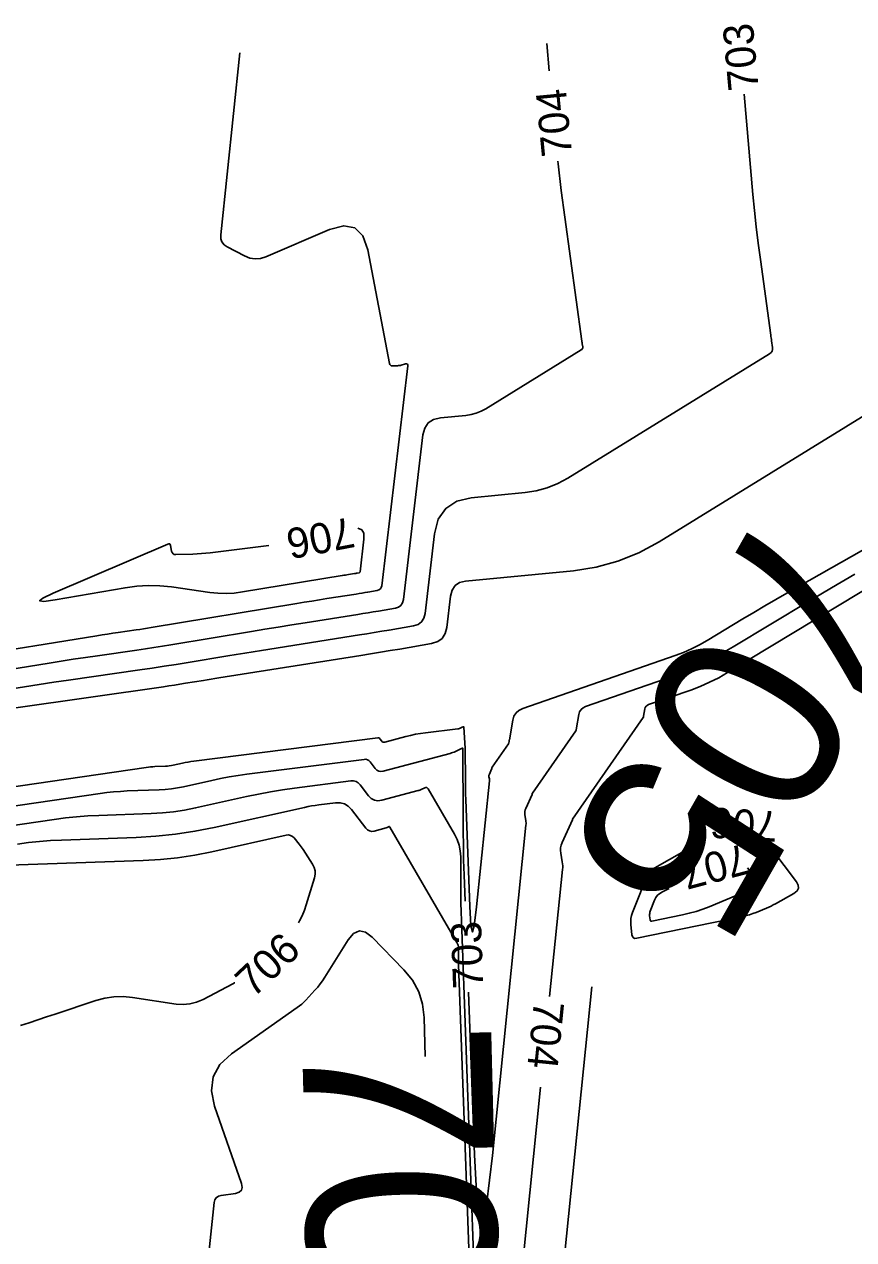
# Model space of a CAD drawing. Extents: x -468541894 to 3393103, y -306086142 to 1227927.
# Drawn here: x 1843132.3 to 1843241.8, y 539573.5 to 539733.9 of the extents above; entities that cross this region are included whole.
import ezdxf

# ---------------------------------------------------------------- set-up
doc = ezdxf.new("R2010")
doc.units = 0
doc.layers.add('DT_X_Contour_Minor', color=7, linetype='Continuous')
doc.layers.add('Level 19', color=7, linetype='Continuous')

msp = doc.modelspace()

# ---------------------------------------------------------------- linework, layer by layer
at = {"layer": 'DT_X_Contour_Minor'}
for points in [[(1843106.87, 539647.58), (1843141.86, 539653.23), (1843142.57, 539653.34), (1843143.28, 539653.45), (1843144, 539653.56), (1843144.71, 539653.66), (1843147.05, 539654), (1843147.55, 539654.07), (1843148.05, 539654.15), (1843148.55, 539654.23), (1843149.05, 539654.31), (1843168.27, 539657.48), (1843169.26, 539657.64), (1843170.25, 539657.8), (1843171.25, 539657.96), (1843172.24, 539658.12), (1843176.12, 539658.73), (1843176.5, 539658.79), (1843176.88, 539658.86), (1843177.26, 539658.92), (1843177.64, 539658.99), (1843178.88, 539659.2), (1843179.12, 539659.27), (1843179.3, 539659.4), (1843179.42, 539659.59), (1843179.48, 539659.83), (1843182.92, 539688.84), (1843182.92, 539688.99), (1843182.87, 539689.08), (1843182.77, 539689.12), (1843182.62, 539689.1), (1843182.06, 539688.93), (1843181.94, 539688.9), (1843181.81, 539688.88), (1843181.69, 539688.87), (1843181.57, 539688.86), (1843180.87, 539688.84), (1843180.73, 539688.85), (1843180.63, 539688.91), (1843180.56, 539689), (1843180.51, 539689.13), (1843177.64, 539704.13), (1843177, 539705.98), (1843175.94, 539707.05), (1843174.47, 539707.33), (1843172.57, 539706.82), (1843164.2, 539703.24), (1843163.48, 539703.02), (1843162.77, 539702.96), (1843162.06, 539703.07), (1843161.37, 539703.35), (1843159.1, 539704.53), (1843158.68, 539704.82), (1843158.39, 539705.19), (1843158.25, 539705.62), (1843158.24, 539706.13), (1843160.77, 539730.14)], [(1843201.58, 539727.77), (1843201.26, 539731.4)], [(1843130.38, 539646.19), (1843132.32, 539646.49), (1843134.26, 539646.79), (1843136.19, 539647.08), (1843138.13, 539647.37), (1843147.56, 539648.73), (1843149.16, 539648.96), (1843150.76, 539649.2), (1843152.36, 539649.45), (1843153.95, 539649.71), (1843159.16, 539650.57), (1843160.28, 539650.76), (1843161.4, 539650.94), (1843162.51, 539651.12), (1843163.63, 539651.29), (1843176.53, 539653.33), (1843177.52, 539653.49), (1843178.5, 539653.65), (1843179.48, 539653.81), (1843180.46, 539653.98), (1843183.67, 539654.53), (1843184.28, 539654.72), (1843184.74, 539655.06), (1843185.05, 539655.53), (1843185.21, 539656.15), (1843186.46, 539666.67), (1843186.95, 539668.59), (1843187.93, 539670.03), (1843189.38, 539670.97), (1843191.31, 539671.43), (1843198.4, 539672.12), (1843199.89, 539672.35), (1843201.33, 539672.74), (1843202.71, 539673.3), (1843204.04, 539674.02), (1843230.68, 539690.43), (1843230.88, 539690.59), (1843231.01, 539690.78), (1843231.07, 539691), (1843231.07, 539691.26), (1843230.95, 539692.14), (1843230.92, 539692.33), (1843230.9, 539692.52), (1843230.87, 539692.71), (1843230.84, 539692.9), (1843229.47, 539702.89), (1843229.19, 539705.03), (1843228.93, 539707.17), (1843228.7, 539709.32), (1843228.49, 539711.47), (1843227.31, 539724.7)], [(1843113.71, 539646.09), (1843135.58, 539649.62), (1843137.18, 539649.87), (1843138.77, 539650.12), (1843140.36, 539650.36), (1843141.96, 539650.59), (1843147.17, 539651.34), (1843148.29, 539651.51), (1843149.4, 539651.68), (1843150.52, 539651.85), (1843151.63, 539652.03), (1843162.27, 539653.79), (1843164.05, 539654.08), (1843165.83, 539654.37), (1843167.6, 539654.65), (1843169.38, 539654.94), (1843176.33, 539656.03), (1843177.01, 539656.14), (1843177.69, 539656.25), (1843178.37, 539656.37), (1843179.05, 539656.48), (1843181.28, 539656.87), (1843181.7, 539657), (1843182.02, 539657.23), (1843182.24, 539657.56), (1843182.35, 539657.99), (1843184.92, 539679.72), (1843185.16, 539680.62), (1843185.62, 539681.3), (1843186.3, 539681.75), (1843187.22, 539681.96), (1843190.57, 539682.29), (1843191.27, 539682.4), (1843191.95, 539682.59), (1843192.61, 539682.85), (1843193.23, 539683.19), (1843205.83, 539690.95), (1843205.92, 539691.02), (1843205.98, 539691.11), (1843206.01, 539691.22), (1843206.01, 539691.34), (1843205.95, 539691.76), (1843205.94, 539691.85), (1843205.93, 539691.93), (1843205.92, 539692.02), (1843205.9, 539692.11), (1843203.65, 539708.46), (1843203.19, 539711.97), (1843202.77, 539715.48), (1843202.73, 539715.83)], [(1843131.19, 539643.7), (1843150.66, 539646.5), (1843151.39, 539646.6), (1843152.12, 539646.71), (1843152.84, 539646.83), (1843153.57, 539646.95), (1843155.95, 539647.34), (1843156.46, 539647.42), (1843156.97, 539647.51), (1843157.47, 539647.59), (1843157.98, 539647.67), (1843176.74, 539650.63), (1843178.02, 539650.83), (1843179.31, 539651.04), (1843180.59, 539651.26), (1843181.88, 539651.47), (1843186.07, 539652.2), (1843186.87, 539652.45), (1843187.47, 539652.88), (1843187.87, 539653.51), (1843188.08, 539654.32), (1843188.57, 539658.46), (1843188.77, 539659.25), (1843189.17, 539659.84), (1843189.77, 539660.23), (1843190.56, 539660.42), (1843204.78, 539661.81), (1843207.78, 539662.27), (1843210.66, 539663.06), (1843213.43, 539664.17), (1843216.09, 539665.61), (1843255.53, 539689.92)], [(1843271.99, 539680.96), (1843232.97, 539658.85), (1843231.51, 539658.01), (1843230.05, 539657.17), (1843228.6, 539656.31), (1843227.16, 539655.45), (1843222.46, 539652.61), (1843221.44, 539652.03), (1843220.39, 539651.5), (1843219.32, 539651.03), (1843218.22, 539650.62), (1843198.09, 539643.61), (1843197.59, 539643.37), (1843197.21, 539643.04), (1843196.94, 539642.6), (1843196.78, 539642.08), (1843196.33, 539639.5), (1843196.32, 539639.44), (1843196.32, 539639.38), (1843196.31, 539639.33), (1843196.3, 539639.27), (1843196.26, 539639.08), (1843196.25, 539639.05), (1843196.24, 539639.01), (1843196.22, 539638.97), (1843196.2, 539638.94), (1843194.06, 539635.86), (1843194.04, 539635.84), (1843194.03, 539635.81), (1843194.03, 539635.79), (1843194.02, 539635.77), (1843194.01, 539635.68), (1843194.01, 539635.67), (1843194.01, 539635.65), (1843194, 539635.63), (1843193.99, 539635.62), (1843193.69, 539634.94), (1843193.66, 539634.86), (1843193.64, 539634.78), (1843193.64, 539634.7), (1843193.64, 539634.61), (1843193.69, 539634.34), (1843193.7, 539634.28), (1843193.7, 539634.22), (1843193.7, 539634.16), (1843193.7, 539634.1), (1843192.01, 539617.45), (1843191.7, 539614.96), (1843191.45, 539614.13), (1843191.24, 539614.97), (1843191.1, 539617.48), (1843190.58, 539631.6), (1843190.56, 539632.33), (1843190.54, 539633.06), (1843190.53, 539633.79), (1843190.53, 539634.52), (1843190.52, 539637.89), (1843190.52, 539637.91), (1843190.52, 539637.93), (1843190.52, 539637.95), (1843190.51, 539637.97), (1843190.51, 539638.03), (1843190.51, 539638.05), (1843190.51, 539638.06), (1843190.51, 539638.07), (1843190.51, 539638.09), (1843190.51, 539638.26), (1843190.5, 539638.3), (1843190.5, 539638.34), (1843190.5, 539638.37), (1843190.5, 539638.41), (1843190.32, 539641.17), (1843190.32, 539641.2), (1843190.3, 539641.22), (1843190.28, 539641.23), (1843190.24, 539641.22), (1843190.11, 539641.16), (1843190.08, 539641.15), (1843190.06, 539641.14), (1843190.03, 539641.13), (1843190, 539641.12), (1843189.76, 539641), (1843189.7, 539640.98), (1843189.65, 539640.96), (1843189.59, 539640.94), (1843189.53, 539640.93), (1843185.28, 539640.43), (1843184.62, 539640.34), (1843183.96, 539640.22), (1843183.3, 539640.08), (1843182.65, 539639.92), (1843179.88, 539639.18), (1843179.76, 539639.16), (1843179.66, 539639.18), (1843179.56, 539639.23), (1843179.48, 539639.32), (1843179.23, 539639.64)], [(1843136.37, 539657.96), (1843145.6, 539659.56), (1843147.14, 539659.77), (1843148.67, 539659.85), (1843150.21, 539659.81), (1843151.75, 539659.66), (1843156.78, 539658.95), (1843157.86, 539658.84), (1843158.94, 539658.81), (1843160.01, 539658.86), (1843161.09, 539659), (1843174.27, 539661.17), (1843174.48, 539661.21), (1843174.68, 539661.24), (1843174.89, 539661.27), (1843175.1, 539661.31), (1843175.91, 539661.44), (1843175.99, 539661.45), (1843176.07, 539661.46), (1843176.15, 539661.47), (1843176.23, 539661.49), (1843176.49, 539661.53), (1843176.54, 539661.55), (1843176.58, 539661.58), (1843176.6, 539661.61), (1843176.62, 539661.66), (1843177.13, 539665.97), (1843177.11, 539666.74), (1843176.84, 539667.22), (1843176.33, 539667.41), (1843176.32, 539667.41)], [(1843164.56, 539665.15), (1843156.85, 539664.17), (1843156.27, 539664.11), (1843155.7, 539664.06), (1843155.12, 539664.02), (1843154.54, 539664), (1843152.3, 539663.94), (1843152.09, 539663.96), (1843151.93, 539664.05), (1843151.82, 539664.19), (1843151.75, 539664.39), (1843151.61, 539665.13), (1843151.56, 539665.27), (1843151.49, 539665.34), (1843151.38, 539665.36), (1843151.25, 539665.33), (1843136.1, 539658.85), (1843134.73, 539658.2), (1843134.32, 539657.84), (1843134.87, 539657.75), (1843136.37, 539657.96)], [(1843251.19, 539664.09), (1843225.15, 539648.36), (1843223.97, 539647.69), (1843222.77, 539647.08), (1843221.53, 539646.54), (1843220.27, 539646.06), (1843214.7, 539644.13), (1843214.52, 539644.04), (1843214.38, 539643.92), (1843214.28, 539643.76), (1843214.22, 539643.57), (1843214.06, 539642.63), (1843214.06, 539642.61), (1843214.05, 539642.59), (1843214.05, 539642.57), (1843214.05, 539642.55), (1843214.04, 539642.48), (1843214.03, 539642.47), (1843214.03, 539642.45), (1843214.02, 539642.44), (1843214.01, 539642.43), (1843204.68, 539629.04), (1843204.68, 539629.03), (1843204.67, 539629.02), (1843204.67, 539629.01), (1843204.67, 539628.99), (1843204.66, 539628.95), (1843204.66, 539628.95), (1843204.66, 539628.94), (1843204.66, 539628.93), (1843204.66, 539628.92)], [(1843241.92, 539661.37), (1843238.86, 539659.56), (1843235.82, 539657.74), (1843225.89, 539651.74), (1843223.74, 539650.52), (1843221.53, 539649.41), (1843219.26, 539648.42), (1843216.94, 539647.54), (1843206.39, 539643.87), (1843206.06, 539643.71), (1843205.8, 539643.48), (1843205.61, 539643.18), (1843205.5, 539642.82), (1843205.2, 539641.06), (1843205.19, 539641.03), (1843205.18, 539640.99), (1843205.18, 539640.95), (1843205.17, 539640.91), (1843205.15, 539640.78), (1843205.14, 539640.76), (1843205.13, 539640.73), (1843205.12, 539640.71), (1843205.11, 539640.68), (1843199.37, 539632.45), (1843199.36, 539632.43), (1843199.35, 539632.41), (1843199.35, 539632.4), (1843199.34, 539632.38), (1843199.34, 539632.32), (1843199.34, 539632.31), (1843199.33, 539632.29), (1843199.33, 539632.28), (1843199.33, 539632.27), (1843198.49, 539630.43), (1843198.41, 539630.23), (1843198.37, 539630.02), (1843198.36, 539629.8), (1843198.38, 539629.58), (1843198.5, 539628.86), (1843198.52, 539628.71), (1843198.53, 539628.55), (1843198.53, 539628.39), (1843198.52, 539628.24), (1843194.11, 539584.64), (1843193.3, 539578.12), (1843192.63, 539575.96), (1843192.1, 539578.16), (1843191.71, 539584.72), (1843190.93, 539606.2)], [(1843179.23, 539639.64), (1843179.17, 539639.7), (1843179.11, 539639.74), (1843179.03, 539639.76), (1843178.95, 539639.76), (1843154.67, 539636.67), (1843154.29, 539636.61), (1843153.92, 539636.55), (1843153.55, 539636.48), (1843153.18, 539636.4), (1843151.97, 539636.14), (1843151.71, 539636.08), (1843151.44, 539636.04), (1843151.18, 539636.02), (1843150.92, 539636), (1843149.55, 539635.95), (1843149.26, 539635.94), (1843148.97, 539635.92), (1843148.68, 539635.89), (1843148.39, 539635.85), (1843123.31, 539632.18)], [(1843190.49, 539618.2), (1843190.37, 539621.69), (1843190.3, 539623.6), (1843190.26, 539625.51), (1843190.23, 539627.42), (1843190.22, 539629.34), (1843190.19, 539638.26), (1843190.19, 539638.26), (1843190.19, 539638.26), (1843190.19, 539638.26), (1843190.19, 539638.26), (1843190.19, 539638.26), (1843190.19, 539638.27), (1843190.19, 539638.27), (1843190.19, 539638.27), (1843190.19, 539638.27), (1843190.19, 539638.27), (1843190.19, 539638.28), (1843190.19, 539638.28), (1843190.19, 539638.28), (1843190.19, 539638.28), (1843190.18, 539638.37), (1843190.18, 539638.39), (1843190.17, 539638.4), (1843190.16, 539638.4), (1843190.15, 539638.39), (1843190.07, 539638.36), (1843190.05, 539638.35), (1843190.04, 539638.35), (1843190.02, 539638.34), (1843190.01, 539638.33), (1843189.21, 539637.96), (1843189.04, 539637.88), (1843188.86, 539637.82), (1843188.69, 539637.76), (1843188.51, 539637.7), (1843179.68, 539635.34), (1843179.37, 539635.3), (1843179.09, 539635.35), (1843178.83, 539635.48), (1843178.61, 539635.71), (1843177.94, 539636.59), (1843177.78, 539636.76), (1843177.61, 539636.86), (1843177.4, 539636.92), (1843177.18, 539636.91), (1843161.68, 539634.94), (1843160.52, 539634.77), (1843159.36, 539634.59), (1843158.21, 539634.37), (1843157.06, 539634.13), (1843153.33, 539633.3), (1843152.52, 539633.14), (1843151.72, 539633.02), (1843150.9, 539632.93), (1843150.09, 539632.89), (1843145.88, 539632.74), (1843144.98, 539632.69), (1843144.08, 539632.62), (1843143.19, 539632.53), (1843142.3, 539632.41), (1843125.38, 539629.94)], [(1843192.32, 539551.95), (1843190.01, 539615.66), (1843189.97, 539616.81), (1843189.94, 539617.96), (1843189.93, 539619.11), (1843189.92, 539620.27), (1843189.91, 539624.03), (1843189.85, 539624.83), (1843189.7, 539625.59), (1843189.45, 539626.33), (1843189.09, 539627.04), (1843185.61, 539633.02), (1843185.53, 539633.13), (1843185.42, 539633.19), (1843185.3, 539633.2), (1843185.17, 539633.16), (1843184.7, 539632.94), (1843184.6, 539632.9), (1843184.5, 539632.86), (1843184.4, 539632.82), (1843184.29, 539632.79), (1843179.49, 539631.51), (1843178.98, 539631.44), (1843178.52, 539631.51), (1843178.11, 539631.73), (1843177.74, 539632.1), (1843176.65, 539633.55), (1843176.39, 539633.81), (1843176.1, 539633.98), (1843175.77, 539634.07), (1843175.41, 539634.06), (1843167.97, 539633.12), (1843166.38, 539632.89), (1843164.8, 539632.64), (1843163.22, 539632.34), (1843161.65, 539632.01), (1843154.9, 539630.51), (1843153.45, 539630.22), (1843151.99, 539630), (1843150.52, 539629.85), (1843149.04, 539629.76), (1843142.15, 539629.52), (1843140.67, 539629.45), (1843139.2, 539629.33), (1843137.73, 539629.18), (1843136.26, 539628.99), (1843127.45, 539627.7)], [(1843192.93, 539519.19), (1843189.64, 539609.82), (1843189.63, 539610.11), (1843189.63, 539610.41), (1843189.62, 539610.71), (1843189.62, 539611.01), (1843189.62, 539611.98), (1843189.6, 539612.18), (1843189.56, 539612.38), (1843189.5, 539612.57), (1843189.41, 539612.76), (1843180.56, 539627.96), (1843180.53, 539628.01), (1843180.49, 539628.03), (1843180.44, 539628.03), (1843180.39, 539628.02), (1843180.21, 539627.93), (1843180.18, 539627.92), (1843180.14, 539627.9), (1843180.1, 539627.89), (1843180.06, 539627.87), (1843178.48, 539627.45), (1843178.16, 539627.41), (1843177.87, 539627.46), (1843177.61, 539627.6), (1843177.38, 539627.83), (1843175.51, 539630.3), (1843175.07, 539630.75), (1843174.58, 539631.05), (1843174.01, 539631.19), (1843173.39, 539631.18), (1843171.17, 539630.9), (1843170.7, 539630.83), (1843170.22, 539630.76), (1843169.75, 539630.67), (1843169.28, 539630.57), (1843157.38, 539627.92), (1843154.83, 539627.42), (1843152.25, 539627.03), (1843149.67, 539626.76), (1843147.06, 539626.6), (1843137.21, 539626.26), (1843135.76, 539626.19), (1843134.31, 539626.07), (1843132.86, 539625.92), (1843131.41, 539625.73)], [(1843204.66, 539628.92), (1843203.29, 539625.93), (1843203.17, 539625.59), (1843203.1, 539625.25), (1843203.08, 539624.9), (1843203.11, 539624.55), (1843203.31, 539623.38), (1843203.35, 539623.13), (1843203.37, 539622.88), (1843203.37, 539622.63), (1843203.35, 539622.38), (1843201.65, 539605.6)], [(1843130.29, 539622.93), (1843147.97, 539623.55), (1843150.26, 539623.68), (1843152.54, 539623.92), (1843154.8, 539624.26), (1843157.05, 539624.71), (1843166.88, 539626.9), (1843167.18, 539626.93), (1843167.45, 539626.88), (1843167.7, 539626.75), (1843167.91, 539626.54), (1843168.57, 539625.72), (1843168.71, 539625.55), (1843168.84, 539625.37), (1843168.97, 539625.18), (1843169.1, 539625), (1843170.36, 539623.06), (1843170.58, 539622.63), (1843170.69, 539622.19), (1843170.71, 539621.74), (1843170.61, 539621.27), (1843169.52, 539617.71), (1843169.27, 539616.99), (1843168.97, 539616.28), (1843168.63, 539615.6), (1843168.49, 539615.36)], [(1843221.05, 539625.7), (1843215.53, 539622.6), (1843215.44, 539622.56), (1843215.36, 539622.52), (1843215.28, 539622.47), (1843215.2, 539622.43), (1843214.92, 539622.3), (1843214.87, 539622.27), (1843214.82, 539622.23), (1843214.79, 539622.18), (1843214.76, 539622.13), (1843212.6, 539616.69), (1843212.47, 539616.31), (1843212.39, 539615.91), (1843212.36, 539615.51), (1843212.38, 539615.11), (1843212.52, 539613.77), (1843212.58, 539613.52), (1843212.7, 539613.36), (1843212.89, 539613.29), (1843213.14, 539613.31)], [(1843213.14, 539613.31), (1843227.14, 539616.18), (1843227.59, 539616.29), (1843228.03, 539616.41), (1843228.47, 539616.56), (1843228.9, 539616.72), (1843230.3, 539617.29), (1843230.6, 539617.42), (1843230.89, 539617.56), (1843231.18, 539617.7), (1843231.46, 539617.86), (1843233.9, 539619.23), (1843234.31, 539619.54), (1843234.5, 539619.91), (1843234.47, 539620.32), (1843234.22, 539620.77), (1843230.98, 539625.05)], [(1843215.15, 539615.56), (1843219.18, 539616.39), (1843220.09, 539616.6), (1843220.98, 539616.85), (1843221.86, 539617.14), (1843222.73, 539617.47), (1843227.12, 539619.28), (1843227.39, 539619.39), (1843227.66, 539619.52), (1843227.92, 539619.65), (1843228.18, 539619.79), (1843229.02, 539620.26), (1843229.16, 539620.37), (1843229.23, 539620.49), (1843229.21, 539620.63), (1843229.13, 539620.79), (1843227.77, 539622.58)], [(1843217.44, 539619.85), (1843216.53, 539619.42), (1843216.19, 539619.22), (1843215.91, 539618.98), (1843215.69, 539618.68), (1843215.51, 539618.33), (1843214.94, 539616.89), (1843214.89, 539616.74), (1843214.86, 539616.59), (1843214.85, 539616.43), (1843214.85, 539616.27), (1843214.91, 539615.74), (1843214.93, 539615.65), (1843214.98, 539615.59), (1843215.05, 539615.56), (1843215.15, 539615.56)], [(1843185.21, 539597.68), (1843185.08, 539602.83), (1843184.88, 539604.6), (1843184.37, 539606.25), (1843183.55, 539607.76), (1843182.42, 539609.14), (1843178.22, 539613.44), (1843177.35, 539614.11), (1843176.53, 539614.28), (1843175.77, 539613.94), (1843175.06, 539613.1), (1843171.98, 539608.16), (1843171.68, 539607.7), (1843171.37, 539607.27), (1843171.03, 539606.85), (1843170.67, 539606.44), (1843169.47, 539605.14), (1843169.21, 539604.87), (1843168.93, 539604.61), (1843168.64, 539604.37), (1843168.34, 539604.15), (1843159.65, 539598.05), (1843158.11, 539596.63), (1843157.22, 539595.01), (1843156.99, 539593.18), (1843157.41, 539591.13), (1843160.95, 539580.92), (1843161.05, 539580.42), (1843160.95, 539580.04), (1843160.66, 539579.78), (1843160.18, 539579.64), (1843158.28, 539579.37), (1843157.92, 539579.26), (1843157.64, 539579.07), (1843157.46, 539578.8), (1843157.38, 539578.43), (1843155.81, 539563.8)], [(1843160.08, 539607.44), (1843160.04, 539607.43), (1843159.81, 539607.31), (1843155.9, 539605.23), (1843155.05, 539604.86), (1843154.17, 539604.63), (1843153.27, 539604.56), (1843152.34, 539604.62), (1843146.58, 539605.5), (1843145.35, 539605.62), (1843144.13, 539605.59), (1843142.93, 539605.41), (1843141.74, 539605.09), (1843136.38, 539603.3), (1843135.23, 539602.92), (1843134.09, 539602.54), (1843132.94, 539602.15), (1843131.79, 539601.77)], [(1843207.2, 539606.88), (1843198.3, 539519.02)], [(1843200.44, 539593.66), (1843196.2, 539551.83)]]:
    msp.add_lwpolyline(points, dxfattribs=at)

# ---------------------------------------------------------------- texts
at = {"layer": 'Level 19'}
for s, height, rotation, p in [('703', 4, 95.1242, (1843229.26, 539725.31)), ('704', 4, 95.4941, (1843204.63, 539716.64)), ('706', 4, 190.8881, (1843175.41, 539668.91)), ('705', 25, 240.3502, (1843230.64, 539672.04)), ('706', 4, 176.2999, (1843231.88, 539630.01)), ('707', 4, 194.7775, (1843227.38, 539625.83)), ('703', 4, 92.0806, (1843192.91, 539606.7)), ('706', 4, 43.2431, (1843162.5, 539605.34)), ('704', 4, 264.2159, (1843199.6, 539605.18)), ('705', 25, 271.4191, (1843168.91, 539602))]:
    msp.add_text(s, height=height, rotation=rotation, dxfattribs=at).set_placement(p)

doc.saveas('drawing.dxf')
